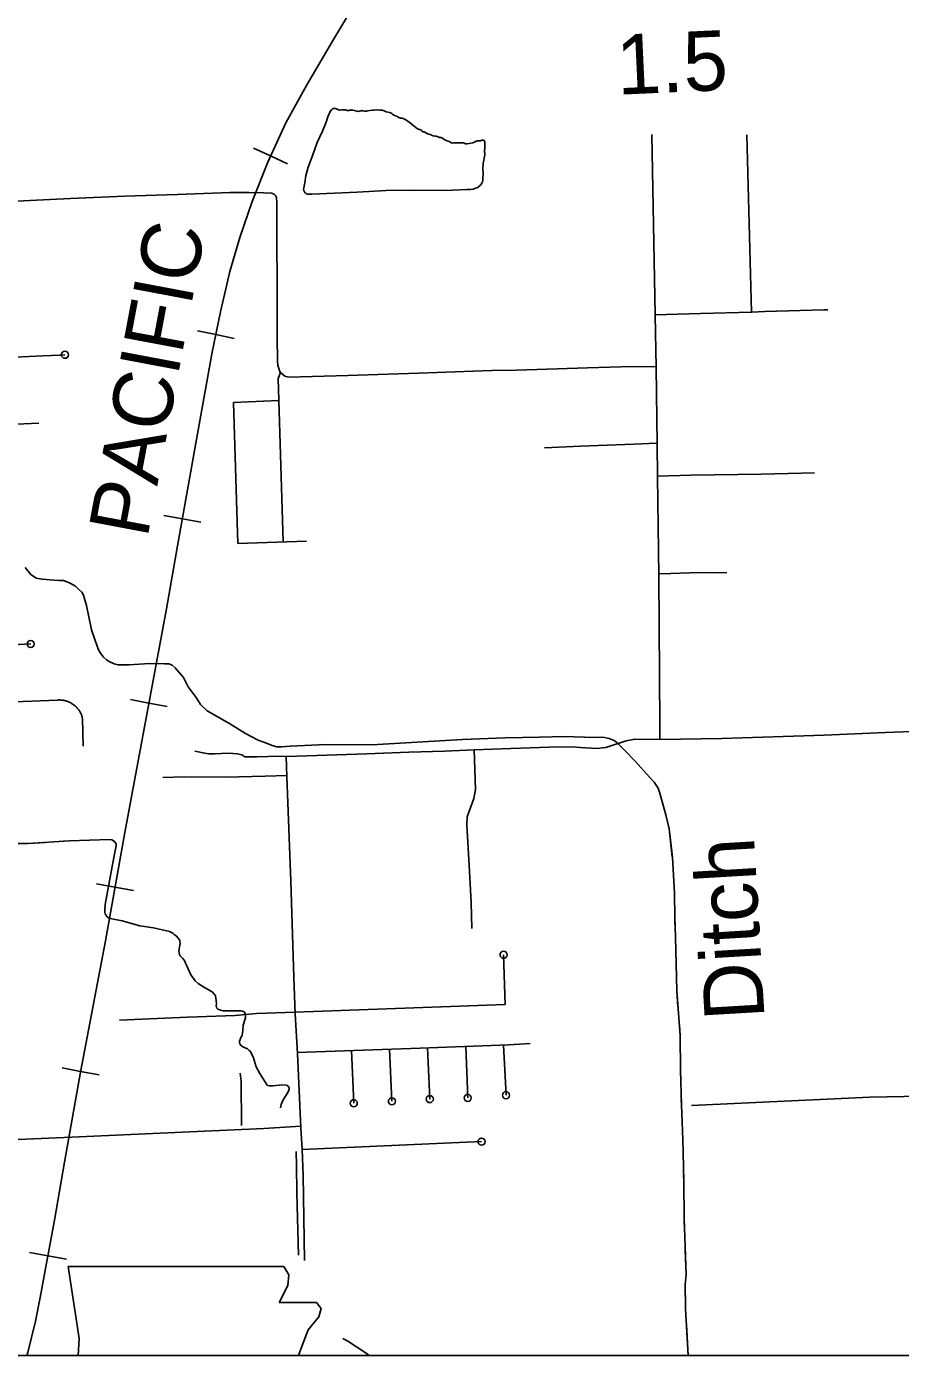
# Model space of a CAD drawing. Extents: x 309348 to 309445, y 336383 to 336484.
# Drawn here: x 309351.301 to 309352.534, y 336395.727 to 336397.601 of the extents above; entities that cross this region are included whole.
import ezdxf

# ---------------------------------------------------------------- set-up
doc = ezdxf.new("R2010")
doc.units = 0
doc.layers.add('R_Annotation', color=7, linetype='Continuous')
doc.layers.add('R_Border Notes', color=7, linetype='Continuous')

msp = doc.modelspace()

# ---------------------------------------------------------------- linework, layer by layer
at = {"layer": 'R_Annotation'}
for p, q in [((309351.645, 336397.4184), (309351.621, 336397.4294)), ((309351.645, 336397.4184), (309351.669, 336397.4074)), ((309351.5678, 336397.1665), (309351.5419, 336397.1717)), ((309351.5678, 336397.1665), (309351.5937, 336397.1612)), ((309351.5205, 336396.9067), (309351.4946, 336396.9113)), ((309351.5205, 336396.9067), (309351.5465, 336396.902)), ((309351.4732, 336396.6469), (309351.4472, 336396.6517)), ((309351.4732, 336396.6469), (309351.4991, 336396.642)), ((309351.4254, 336396.3871), (309351.3994, 336396.3918)), ((309351.4254, 336396.3871), (309351.4514, 336396.3825)), ((309351.377, 336396.1275), (309351.3511, 336396.1324)), ((309351.377, 336396.1275), (309351.403, 336396.1226)), ((309351.3308, 336395.8675), (309351.3048, 336395.8722)), ((309351.3308, 336395.8675), (309351.3568, 336395.8628)), ((309351.3747, 336395.7509), (309351.3595, 336395.8525)), ((309351.3595, 336395.8525), (309351.6639, 336395.8523)), ((309351.6639, 336395.8523), (309351.6709, 336395.8406)), ((309351.6641, 336395.8525), (309351.6641, 336395.8525)), ((309351.6709, 336395.8406), (309351.6692, 336395.8254)), ((309351.6692, 336395.8254), (309351.6573, 336395.8017)), ((309351.6573, 336395.8017), (309351.7098, 336395.8017)), ((309351.7098, 336395.8017), (309351.7166, 336395.7932)), ((309351.7132, 336395.7814), (309351.6979, 336395.7628)), ((309351.7166, 336395.7932), (309351.7132, 336395.7814)), ((309351.6895, 336395.7408), (309351.6979, 336395.7628)), ((309351.3736, 336395.7269), (309351.3747, 336395.7509)), ((309351.6895, 336395.7408), (309351.6843, 336395.7269))]:
    msp.add_line(p, q, dxfattribs=at)
for points in [[(309351.301, 336395.7269), (309351.3023, 336395.7312), (309351.3132, 336395.7754), (309351.3199, 336395.8087), (309351.3289, 336395.8572), (309351.3399, 336395.9178), (309351.3544, 336395.9996), (309351.3768, 336396.1262), (309351.4119, 336396.3116), (309351.4392, 336396.4643), (309351.498, 336396.78), (309351.5137, 336396.8685), (309351.5476, 336397.0581), (309351.5628, 336397.1417), (309351.5743, 336397.1987), (309351.5876, 336397.2557), (309351.6016, 336397.3035), (309351.6191, 336397.3544), (309351.6409, 336397.4096), (309351.6664, 336397.4653), (309351.6955, 336397.518), (309351.7324, 336397.5804), (309351.759, 336397.6248)], [(309351.301, 336395.7269), (309351.3023, 336395.7312), (309351.3132, 336395.7754), (309351.3199, 336395.8087), (309351.3289, 336395.8572), (309351.3399, 336395.9178), (309351.3544, 336395.9996), (309351.3768, 336396.1262), (309351.4119, 336396.3116), (309351.4392, 336396.4643), (309351.498, 336396.78), (309351.5137, 336396.8685), (309351.5476, 336397.0581), (309351.5628, 336397.1417), (309351.5743, 336397.1987), (309351.5876, 336397.2557), (309351.6016, 336397.3035), (309351.6191, 336397.3544), (309351.6409, 336397.4096), (309351.6664, 336397.4653), (309351.6955, 336397.518), (309351.7324, 336397.5804), (309351.759, 336397.6248)], [(309351.7671, 336397.3675), (309351.7032, 336397.3644), (309351.6981, 336397.3644), (309351.696, 336397.3647), (309351.6951, 336397.3655), (309351.694, 336397.3664), (309351.6934, 336397.3671), (309351.6928, 336397.368), (309351.6917, 336397.3696), (309351.6915, 336397.3717), (309351.6917, 336397.3737), (309351.6932, 336397.3805), (309351.6948, 336397.391), (309351.6979, 336397.4026), (309351.7046, 336397.4198), (309351.7107, 336397.4374), (309351.7184, 336397.4535), (309351.7235, 336397.466), (309351.7259, 336397.4736), (309351.7291, 336397.4812), (309351.7311, 336397.4833), (309351.7326, 336397.4847), (309351.7335, 336397.4854), (309351.734, 336397.4856), (309351.7345, 336397.4856), (309351.7352, 336397.4856), (309351.7364, 336397.4855), (309351.738, 336397.4847), (309351.74, 336397.484), (309351.7426, 336397.4832), (309351.7449, 336397.4833), (309351.7475, 336397.4833), (309351.7492, 336397.4833), (309351.7509, 336397.4833), (309351.7517, 336397.4829), (309351.7532, 336397.4825), (309351.7541, 336397.4825), (309351.7552, 336397.4826), (309351.7564, 336397.4828), (309351.7574, 336397.4829), (309351.7582, 336397.4831), (309351.7594, 336397.4832), (309351.7607, 336397.4832), (309351.7632, 336397.4825), (309351.7666, 336397.4815), (309351.7685, 336397.4813), (309351.77, 336397.4814), (309351.772, 336397.4819), (309351.7732, 336397.4823), (309351.7741, 336397.4824), (309351.7754, 336397.4821), (309351.7772, 336397.4816), (309351.7785, 336397.4814), (309351.7804, 336397.4816), (309351.782, 336397.4821), (309351.7849, 336397.4824), (309351.7891, 336397.4832), (309351.7914, 336397.4832), (309351.7954, 336397.4833), (309351.7993, 336397.4832), (309351.8026, 336397.4828), (309351.8055, 336397.482), (309351.808, 336397.4809), (309351.8133, 336397.4795), (309351.816, 336397.4782), (309351.8176, 336397.4771), (309351.82, 336397.4754), (309351.823, 336397.4745), (309351.8242, 336397.4738), (309351.8258, 336397.4725), (309351.8272, 336397.472), (309351.8284, 336397.4719), (309351.8304, 336397.4718), (309351.8322, 336397.4713), (309351.835, 336397.4699), (309351.8403, 336397.4665), (309351.8477, 336397.4603), (309351.8521, 336397.4569), (309351.8536, 336397.456), (309351.8548, 336397.4557), (309351.8557, 336397.4557), (309351.8564, 336397.4554), (309351.8578, 336397.4548), (309351.8591, 336397.453), (309351.8605, 336397.4523), (309351.8618, 336397.4523), (309351.8628, 336397.452), (309351.8649, 336397.4508), (309351.868, 336397.449), (309351.8695, 336397.4489), (309351.8706, 336397.4486), (309351.8719, 336397.4478), (309351.8743, 336397.4468), (309351.8772, 336397.4464), (309351.8788, 336397.4464), (309351.8803, 336397.446), (309351.8816, 336397.4452), (309351.8832, 336397.4443), (309351.8843, 336397.4443), (309351.8857, 336397.4443), (309351.8877, 336397.4437)], [(309351.8877, 336397.4437), (309351.8893, 336397.4423), (309351.8917, 336397.4408), (309351.8941, 336397.4399), (309351.8955, 336397.4393), (309351.8971, 336397.439), (309351.8979, 336397.4385), (309351.8988, 336397.4381), (309351.8994, 336397.4373), (309351.9003, 336397.4368), (309351.9013, 336397.4367), (309351.9037, 336397.4368), (309351.9079, 336397.437), (309351.9111, 336397.437), (309351.9139, 336397.4371), (309351.9167, 336397.4368), (309351.9181, 336397.4363), (309351.92, 336397.4356), (309351.9219, 336397.4356), (309351.9253, 336397.4361), (309351.9306, 336397.4369), (309351.9329, 336397.4378), (309351.935, 336397.4393), (309351.9364, 336397.4397), (309351.9388, 336397.4397), (309351.941, 336397.4399), (309351.943, 336397.4406), (309351.9441, 336397.4407), (309351.945, 336397.4408), (309351.9463, 336397.4403), (309351.9468, 336397.4395), (309351.9474, 336397.4381), (309351.9474, 336397.4366), (309351.9474, 336397.4305), (309351.9468, 336397.4242), (309351.9472, 336397.422), (309351.9471, 336397.42), (309351.945, 336397.4077), (309351.9447, 336397.4005), (309351.9452, 336397.3942), (309351.9447, 336397.3862), (309351.9447, 336397.3839), (309351.9441, 336397.3821), (309351.9432, 336397.38), (309351.9408, 336397.377), (309351.9363, 336397.3736), (309351.9343, 336397.373), (309351.9307, 336397.3715), (309351.9273, 336397.3711), (309351.9217, 336397.3713), (309351.9015, 336397.3703), (309351.893, 336397.3696), (309351.8399, 336397.3703), (309351.808, 336397.3696), (309351.7671, 336397.3675)], [(309352.1832, 336397.4485), (309352.1878, 336397.1944)], [(309352.3168, 336397.448), (309352.3235, 336397.1983)], [(309351.1156, 336397.3468), (309351.1973, 336397.3498), (309351.3051, 336397.3554), (309351.3625, 336397.3583), (309351.4388, 336397.3617), (309351.5137, 336397.3639), (309351.5877, 336397.3669), (309351.6141, 336397.3669), (309351.6348, 336397.3665), (309351.6461, 336397.3658), (309351.6501, 336397.3644), (309351.6519, 336397.3626), (309351.6532, 336397.3597), (309351.6536, 336397.3528), (309351.6537, 336397.333), (309351.6537, 336397.3292)], [(309351.6537, 336397.3292), (309351.6539, 336397.2889), (309351.6541, 336397.2476), (309351.6543, 336397.2067), (309351.6544, 336397.1652), (309351.6549, 336397.1273), (309351.6549, 336397.1266), (309351.655, 336397.1258), (309351.6551, 336397.1251), (309351.6552, 336397.1244), (309351.6553, 336397.1236), (309351.6554, 336397.1229), (309351.6558, 336397.1214), (309351.656, 336397.1207), (309351.6563, 336397.12), (309351.6568, 336397.1186), (309351.657, 336397.1171), (309351.6573, 336397.1164), (309351.6592, 336397.113)], [(309352.1878, 336397.1944), (309352.2517, 336397.1962), (309352.3235, 336397.1983)], [(309352.1878, 336397.1944), (309352.189, 336397.1201)], [(309352.3235, 336397.1983), (309352.3426, 336397.1989), (309352.4257, 336397.2013), (309352.4315, 336397.2015)], [(309351.1195, 336397.1272), (309351.1855, 336397.1306), (309351.2541, 336397.1332), (309351.3236, 336397.1368), (309351.3475, 336397.1376), (309351.3548, 336397.1381)], [(309351.6592, 336397.113), (309351.6557, 336397.1047), (309351.6628, 336396.8741)], [(309351.6592, 336397.113), (309351.6651, 336397.1077), (309351.6709, 336397.1063), (309351.7539, 336397.1088), (309351.8539, 336397.1121), (309351.9571, 336397.1157), (309351.992, 336397.1164), (309352.092, 336397.1196), (309352.1553, 336397.1214), (309352.189, 336397.1211)], [(309352.189, 336397.1201), (309352.1904, 336397.0118)], [(309351.5988, 336396.8721), (309351.5927, 336397.0706), (309351.6561, 336397.0735)], [(309351.2313, 336397.0373), (309351.2859, 336397.04), (309351.3179, 336397.0414)], [(309352.0313, 336397.0069), (309352.0825, 336397.0091), (309352.1574, 336397.0119), (309352.1894, 336397.0133)], [(309352.1904, 336397.0118), (309352.1911, 336396.9657)], [(309352.191, 336396.9671), (309352.2378, 336396.9684), (309352.3372, 336396.9697), (309352.4123, 336396.9714)], [(309352.1911, 336396.9657), (309352.1928, 336396.8269)], [(309351.6957, 336396.8751), (309351.5988, 336396.8721)], [(309352.2075, 336396.4696), (309352.2026, 336396.4892), (309352.1978, 336396.5063), (309352.1943, 336396.52), (309352.1921, 336396.5269), (309352.1864, 336396.5351), (309352.1798, 336396.5425), (309352.1593, 336396.5651), (309352.1448, 336396.5802), (309352.1337, 336396.5913), (309352.13, 336396.5941), (309352.1228, 336396.597), (309352.114, 336396.5987), (309352.1012, 336396.5984), (309352.0878, 336396.5987), (309352.059, 336396.5995), (309352.0243, 336396.5987), (309351.9759, 336396.5978), (309351.9158, 336396.5955), (309351.7881, 336396.5879), (309351.7235, 336396.5884), (309351.6728, 336396.5859), (309351.6605, 336396.585), (309351.6537, 336396.585), (309351.6471, 336396.587), (309351.6392, 336396.5901), (309351.6275, 336396.5944), (309351.6098, 336396.6041), (309351.5859, 336396.6183), (309351.5557, 336396.636), (309351.5463, 336396.6449), (309351.5398, 336396.6545), (309351.5286, 336396.6699), (309351.5221, 336396.6828), (309351.5104, 336396.6967), (309351.5061, 336396.7004), (309351.5016, 336396.7021), (309351.4953, 336396.7021), (309351.4745, 336396.7027), (309351.4449, 336396.7007), (309351.4298, 336396.7007), (309351.4244, 336396.7024), (309351.4173, 336396.7056), (309351.4133, 336396.7078), (309351.4093, 336396.7115), (309351.405, 336396.7172), (309351.4024, 336396.7221), (309351.3976, 336396.7349), (309351.3925, 336396.7503), (309351.3885, 336396.7683), (309351.3851, 336396.7845), (309351.3811, 336396.799), (309351.3785, 336396.8033), (309351.374, 336396.8073), (309351.3698, 336396.8117), (309351.3613, 336396.8164), (309351.353, 336396.8198), (309351.3465, 336396.8199), (309351.3398, 336396.8203), (309351.3226, 336396.8215), (309351.3141, 336396.8232), (309351.3066, 336396.8284), (309351.2988, 336396.838)], [(309352.1927, 336396.8289), (309352.2099, 336396.8295), (309352.25, 336396.8309), (309352.2759, 336396.8306), (309352.2886, 336396.8311)], [(309352.1928, 336396.8269), (309352.1943, 336396.6163), (309352.1943, 336396.5953)], [(309351.1251, 336396.7205), (309351.3065, 336396.7302)], [(309351.1278, 336396.6426), (309351.3438, 336396.6511), (309351.345, 336396.6512), (309351.3461, 336396.6513), (309351.3473, 336396.6513), (309351.3485, 336396.6512), (309351.3497, 336396.6511), (309351.3508, 336396.651), (309351.352, 336396.6508), (309351.3532, 336396.6506), (309351.3543, 336396.6504), (309351.3555, 336396.6501), (309351.3566, 336396.6498), (309351.3577, 336396.6494), (309351.3588, 336396.649), (309351.3599, 336396.6486), (309351.361, 336396.6481), (309351.3621, 336396.6476), (309351.3631, 336396.6471), (309351.3642, 336396.6465), (309351.3652, 336396.6459), (309351.3661, 336396.6452), (309351.3671, 336396.6445), (309351.368, 336396.6438), (309351.369, 336396.6431), (309351.3698, 336396.6423), (309351.3707, 336396.6415), (309351.3715, 336396.6406), (309351.3723, 336396.6398), (309351.3731, 336396.6389), (309351.3738, 336396.638), (309351.3745, 336396.637), (309351.3752, 336396.636), (309351.3759, 336396.6351), (309351.3765, 336396.634), (309351.377, 336396.633), (309351.3774, 336396.6322), (309351.3777, 336396.6315), (309351.378, 336396.6307), (309351.3783, 336396.6299), (309351.3786, 336396.6291), (309351.3788, 336396.6282), (309351.379, 336396.6274), (309351.3791, 336396.6266), (309351.3793, 336396.6258), (309351.3794, 336396.6249), (309351.3806, 336396.5862)], [(309352.7317, 336396.613), (309352.6785, 336396.6116), (309352.5129, 336396.6052), (309352.4263, 336396.6018), (309352.2816, 336396.5971), (309352.1943, 336396.5953)], [(309352.1943, 336396.5953), (309352.1592, 336396.5959), (309352.1468, 336396.5934), (309352.1182, 336396.5841), (309352.1055, 336396.5829), (309352.0822, 336396.5841), (309352.0704, 336396.585), (309352.0381, 336396.5847), (309351.9838, 336396.5829), (309351.9325, 336396.5807)], [(309351.5379, 336396.5792), (309351.5497, 336396.5765), (309351.5576, 336396.5752), (309351.5665, 336396.5752), (309351.585, 336396.576), (309351.5982, 336396.5754), (309351.6043, 336396.5739), (309351.6085, 336396.5712), (309351.613, 336396.571), (309351.6256, 336396.5712), (309351.658, 336396.5722), (309351.6671, 336396.5716)], [(309351.6671, 336396.5716), (309351.696, 336396.5725), (309351.7808, 336396.5752), (309351.8403, 336396.5775), (309351.8904, 336396.5792), (309351.9325, 336396.5807)], [(309351.6671, 336396.5716), (309351.668, 336396.5433)], [(309351.9325, 336396.5807), (309351.9341, 336396.5252), (309351.9316, 336396.5122), (309351.9223, 336396.4864), (309351.9219, 336396.4749), (309351.9252, 336396.4184), (309351.928, 336396.3656), (309351.9291, 336396.3289)], [(309351.668, 336396.5445), (309351.6374, 336396.5439), (309351.582, 336396.5422), (309351.5236, 336396.543), (309351.4931, 336396.5418)], [(309351.668, 336396.5433), (309351.6735, 336396.3957), (309351.678, 336396.2598)], [(309352.2075, 336396.4696), (309352.2075, 336396.4696), (309352.2119, 336396.4302)], [(309352.2075, 336396.4696), (309352.212, 336396.4294), (309352.2149, 336396.3784), (309352.2154, 336396.345), (309352.2163, 336396.3168), (309352.2183, 336396.241), (309352.2228, 336396.178), (309352.2234, 336396.1293), (309352.2248, 336396.0803), (309352.2265, 336396.0313), (309352.2271, 336396.0125), (309352.228, 336395.9726), (309352.2285, 336395.9201), (309352.2314, 336395.8409), (309352.23, 336395.8269), (309352.2305, 336395.7927), (309352.2341, 336395.7269)], [(309351.2032, 336396.4493), (309351.3027, 336396.4488), (309351.361, 336396.4528), (309351.4182, 336396.4544), (309351.4212, 336396.4539), (309351.4234, 336396.4527), (309351.4253, 336396.451), (309351.4264, 336396.4497), (309351.4269, 336396.448), (309351.4269, 336396.4455), (309351.4236, 336396.4289), (309351.4116, 336396.3628), (309351.411, 336396.3546), (309351.4111, 336396.3519), (309351.4114, 336396.3494), (309351.4124, 336396.348), (309351.4138, 336396.346), (309351.4148, 336396.3448), (309351.4162, 336396.3438), (309351.4193, 336396.343), (309351.4212, 336396.3426)], [(309351.2475, 336396.449), (309351.3027, 336396.4488), (309351.3267, 336396.4504)], [(309351.353, 336396.4522), (309351.361, 336396.4528), (309351.4182, 336396.4544), (309351.4212, 336396.4539), (309351.4234, 336396.4527), (309351.4253, 336396.451), (309351.4264, 336396.4497), (309351.4269, 336396.448), (309351.4269, 336396.4456)], [(309352.2134, 336396.4039), (309352.2149, 336396.3784), (309352.2154, 336396.345), (309352.216, 336396.3247)], [(309351.4212, 336396.3426), (309351.4358, 336396.3397), (309351.4604, 336396.3326), (309351.4799, 336396.3298)], [(309351.4799, 336396.3298), (309351.5025, 336396.3248), (309351.507, 336396.3223), (309351.5091, 336396.3206), (309351.5121, 336396.3181), (309351.5145, 336396.3154), (309351.5161, 336396.3136), (309351.5168, 336396.3121), (309351.517, 336396.3104), (309351.5173, 336396.308), (309351.5161, 336396.3005), (309351.5157, 336396.2966), (309351.5159, 336396.2945), (309351.5164, 336396.2922), (309351.5175, 336396.2904), (309351.5213, 336396.2865), (309351.524, 336396.2827), (309351.5248, 336396.2803), (309351.5264, 336396.2771), (309351.5323, 336396.2637), (309351.5386, 336396.2552), (309351.5428, 336396.2514), (309351.5518, 336396.2459), (309351.5625, 336396.2396), (309351.566, 336396.2359), (309351.5671, 336396.234), (309351.5679, 336396.2313), (309351.5681, 336396.2271), (309351.5685, 336396.2233), (309351.5684, 336396.2196), (309351.5688, 336396.2184), (309351.5693, 336396.2168), (309351.5706, 336396.2154), (309351.5722, 336396.2146), (309351.5743, 336396.2136), (309351.5779, 336396.2127), (309351.5869, 336396.2127), (309351.5925, 336396.2127), (309351.6, 336396.213), (309351.6033, 336396.213), (309351.6053, 336396.2125), (309351.6077, 336396.2115), (309351.6088, 336396.2101), (309351.6095, 336396.2073), (309351.6095, 336396.2052), (309351.6095, 336396.2035), (309351.6085, 336396.2002), (309351.6064, 336396.1927), (309351.606, 336396.1849), (309351.6056, 336396.1816), (309351.6047, 336396.1779), (309351.6032, 336396.1751), (309351.6019, 336396.1722), (309351.6012, 336396.17), (309351.6011, 336396.1681), (309351.6015, 336396.1665), (309351.6029, 336396.1644), (309351.6057, 336396.1622), (309351.6091, 336396.1605), (309351.6122, 336396.1594), (309351.615, 336396.1571), (309351.6169, 336396.1549), (309351.6183, 336396.1522), (309351.6203, 336396.148), (309351.6247, 336396.1339), (309351.63, 336396.1245), (309351.6391, 336396.1092), (309351.6407, 336396.1077), (309351.6433, 336396.1071), (309351.6484, 336396.1071), (309351.6569, 336396.1082), (309351.6612, 336396.1084), (309351.6664, 336396.1082), (309351.6682, 336396.1077), (309351.6701, 336396.1061), (309351.6714, 336396.1037), (309351.6714, 336396.1023), (309351.6708, 336396.1009), (309351.6693, 336396.0976), (309351.6628, 336396.0874), (309351.6598, 336396.0808), (309351.6591, 336396.0761)], [(309351.9738, 336396.2919), (309351.9759, 336396.2218)], [(309352.2168, 336396.2983), (309352.2183, 336396.241), (309352.2199, 336396.2191)], [(309351.678, 336396.2598), (309351.6798, 336396.2086)], [(309351.6797, 336396.2109), (309351.9759, 336396.2218)], [(309351.6797, 336396.2109), (309351.6249, 336396.209), (309351.5952, 336396.2065), (309351.5276, 336396.2039), (309351.432, 336396.1997)], [(309351.6798, 336396.2086), (309351.6828, 336396.1527)], [(309352.2218, 336396.1928), (309352.2228, 336396.178), (309352.2234, 336396.1293), (309352.2239, 336396.1136)], [(309351.6827, 336396.1542), (309351.8561, 336396.1602), (309351.981, 336396.1648), (309352.0112, 336396.167)], [(309351.7592, 336396.1569), (309351.7624, 336396.0825)], [(309351.8128, 336396.1587), (309351.8162, 336396.0853)], [(309351.8665, 336396.1606), (309351.8697, 336396.0884)], [(309351.9205, 336396.1626), (309351.9232, 336396.0901)], [(309351.9739, 336396.1646), (309351.9772, 336396.0939)], [(309351.6828, 336396.1527), (309351.6877, 336396.048)], [(309351.602, 336396.125), (309351.6037, 336396.1135), (309351.6041, 336396.051)], [(309352.2389, 336396.0795), (309352.4907, 336396.091), (309352.661, 336396.0944), (309352.7544, 336396.0963), (309352.8924, 336396.0972), (309353.0353, 336396.0999), (309353.1151, 336396.1014), (309353.271, 336396.1031)], [(309352.2246, 336396.0872), (309352.2248, 336396.0803), (309352.2265, 336396.0313), (309352.2271, 336396.0125), (309352.2272, 336396.008)], [(309351.6876, 336396.0503), (309351.6353, 336396.0469), (309351.5413, 336396.0428), (309351.3647, 336396.0346), (309351.2781, 336396.0308), (309351.1803, 336396.0272)], [(309351.6877, 336396.048), (309351.6894, 336396.0173)], [(309351.6894, 336396.0173), (309351.9427, 336396.0284)], [(309351.6811, 336396.0145), (309351.6818, 336395.9946), (309351.6819, 336395.9564), (309351.6842, 336395.8685)], [(309351.6894, 336396.0173), (309351.6908, 336395.9807), (309351.6929, 336395.8607)], [(309352.2278, 336395.9816), (309352.228, 336395.9726), (309352.2285, 336395.9201), (309352.2292, 336395.9024)], [(309352.2301, 336395.876), (309352.2314, 336395.8409), (309352.2309, 336395.8365)], [(309352.2309, 336395.8365), (309352.23, 336395.8269), (309352.2305, 336395.7969)], [(309352.2317, 336395.7705), (309352.2341, 336395.7269)], [(309351.7471, 336395.7508), (309351.7542, 336395.7469), (309351.7786, 336395.7309), (309351.7843, 336395.7269)], [(309351.7471, 336395.7508), (309351.7542, 336395.7469), (309351.7786, 336395.7309), (309351.7806, 336395.7295)]]:
    msp.add_lwpolyline(points, dxfattribs=at)
for centre in [(309351.3548, 336397.1381), (309351.3065, 336396.7302), (309351.9738, 336396.2919), (309351.7624, 336396.0825), (309351.8162, 336396.0853), (309351.8697, 336396.0884), (309351.9232, 336396.0901), (309351.9772, 336396.0939), (309351.9427, 336396.0284)]:
    msp.add_circle(centre, 0.005, dxfattribs=at)
at = {"layer": 'R_Border Notes'}
msp.add_line((309356.3641, 336395.7269), (309347.6607, 336395.7269), dxfattribs=at)

# ---------------------------------------------------------------- texts
at = {"layer": 'R_Annotation'}
for s, rotation, p in [('1.5', 2.6207, (309352.1348, 336397.5047)), ('PACIFIC', 79.3327, (309351.471, 336396.8779)), ('Ditch', 93.3676, (309352.3422, 336396.2022))]:
    msp.add_text(s, height=0.08451, rotation=rotation, dxfattribs=at).set_placement(p)

doc.saveas('drawing.dxf')
